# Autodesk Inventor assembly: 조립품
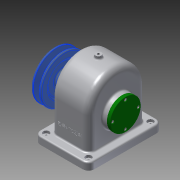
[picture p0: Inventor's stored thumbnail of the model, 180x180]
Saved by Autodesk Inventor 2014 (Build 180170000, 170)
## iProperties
Created: 2016-10
Part Number: 조립품
Document SubType Name: Assembly
Designer: USER
Author: USER
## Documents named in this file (15)
- C:\Users\USER\Desktop\461008V1009\조립품.iam
- C:\Users\USER\Desktop\461008V1009\본체.ipt
- C:\Users\USER\Desktop\461008V1009\V-벨트풀리.ipt
- C:\Users\USER\Desktop\461008V1009\뒤커버.ipt
- C:\Users\USER\Desktop\461008V1009\멈춤나사 - M4x10.ipt
- C:\Users\USER\Desktop\461008V1009\베어링 6203.ipt
- C:\Users\USER\Desktop\461008V1009\볼트 M3 x 8.ipt
- C:\Users\USER\Desktop\461008V1009\볼트 M3 x 10.ipt
- C:\Users\USER\Desktop\461008V1009\부시.ipt
- C:\Users\USER\Desktop\461008V1009\스퍼기어.ipt
- C:\Users\USER\Desktop\461008V1009\앞커버.ipt
- C:\Users\USER\Desktop\461008V1009\오일씰 28 40 8.ipt
- C:\Users\USER\Desktop\461008V1009\축.ipt
- C:\Users\USER\Desktop\461008V1009\키 - 5 x 5 x 18.ipt
- C:\Users\USER\Desktop\461008V1009\키 - 6 x 6 x 22.ipt
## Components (9 placed, 3 different names)
1. V-벨트풀리:1
2. ISO 4762 M3 x 10:1
3. ISO 4762 M3 x 10:2
4. ISO 4762 M3 x 10:3
5. ISO 4762 M3 x 10:4
6. ISO 4762 M3 x 8:1
7. ISO 4762 M3 x 8:2
8. ISO 4762 M3 x 8:3
9. ISO 4762 M3 x 8:4
